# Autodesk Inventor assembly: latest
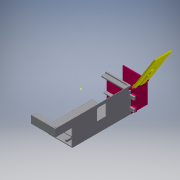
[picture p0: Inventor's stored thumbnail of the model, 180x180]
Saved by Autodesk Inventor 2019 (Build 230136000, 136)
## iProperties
Created: 2019-08
Part Number: latest
Material: 常规
Document SubType Name: Assembly
Designer: YOGA3
Author: YOGA3
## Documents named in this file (9)
- D:\Yi\paper_assay\CAD Model\Device\latest.iam
- D:\Yi\paper_assay\CAD Model\Device\Part_top_v2.ipt
- D:\Yi\paper_assay\CAD Model\Device\Part _left_v3.ipt
- D:\Yi\paper_assay\CAD Model\Device\Part_top_left.ipt
- C:\Users\YOGA3\Desktop\new work\metalVCSEL_Holder_short.ipt
- D:\Yi\paper_assay\CAD Model\Device\glass_holder_v2.ipt
- D:\Yi\paper_assay\CAD Model\Device\separated part_v1.ipt
- D:\Yi\Laptop\cAir_ElectroStaticPrecipitator\models\device\HikeMic_CAD\Schematics\Sensor_Board.ipt
- D:\Yi\Laptop\cAir_ElectroStaticPrecipitator\models\device\HikeMic_CAD\Sensor_Holder.ipt
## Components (8 placed, 8 different names)
1. Part_top_v2:1 — 配合:5, 配合:6, 配合:7, 配合:10, 配合:14, Mate:16, Mate:17
2. Part _left_v3:1 — 配合:1, 表面齐平:1, 配合:5, 配合:6, 配合:7, 配合:8, 配合:9, 角度:1, 配合:15, Mate:18, Mate:19, Mate:20
3. Part_top_left:1 — 配合:1, 表面齐平:1, 配合:11, 配合:12, 配合:13
4. metalVCSEL_Holder_short:1 — 配合:11, 配合:12, 配合:13
5. glass_holder_v2:1 — 配合:8, 配合:9, 角度:1
6. separated part_v1:1 — 配合:10, 配合:14, 配合:15
7. Sensor_Board:1 — Mate:18, Mate:19, Mate:20, Mate:21, Mate:22, Mate:23
8. Sensor_Holder:1 — Mate:21, Mate:22, Mate:23
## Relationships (22: Mate 20, Flush 1, Angle 1)
- 配合:1 [Mate]: Part _left_v3:1 ↔ Part_top_left:1
- 表面齐平:1 [Flush]: Part _left_v3:1 ↔ Part_top_left:1
- 配合:5 [Mate]: Part_top_v2:1 ↔ Part _left_v3:1
- 配合:6 [Mate]: Part_top_v2:1 ↔ Part _left_v3:1
- 配合:7 [Mate]: Part_top_v2:1 ↔ Part _left_v3:1
- 配合:8 [Mate]: Part _left_v3:1 ↔ glass_holder_v2:1
- 配合:9 [Mate]: Part _left_v3:1 ↔ glass_holder_v2:1
- 角度:1 [Angle]: Part _left_v3:1 ↔ glass_holder_v2:1
- 配合:10 [Mate]: Part_top_v2:1 ↔ separated part_v1:1
- 配合:11 [Mate]: Part_top_left:1 ↔ metalVCSEL_Holder_short:1
- 配合:12 [Mate]: Part_top_left:1 ↔ metalVCSEL_Holder_short:1
- 配合:13 [Mate]: Part_top_left:1 ↔ metalVCSEL_Holder_short:1
- 配合:14 [Mate]: Part_top_v2:1 ↔ separated part_v1:1
- 配合:15 [Mate]: Part _left_v3:1 ↔ separated part_v1:1
- Mate:16: Part_top_v2:1
- Mate:17: Part_top_v2:1
- Mate:18: Part _left_v3:1 ↔ Sensor_Board:1
- Mate:19: Part _left_v3:1 ↔ Sensor_Board:1
- Mate:20: Part _left_v3:1 ↔ Sensor_Board:1
- Mate:21: Sensor_Board:1 ↔ Sensor_Holder:1
- Mate:22: Sensor_Board:1 ↔ Sensor_Holder:1
- Mate:23: Sensor_Board:1 ↔ Sensor_Holder:1
